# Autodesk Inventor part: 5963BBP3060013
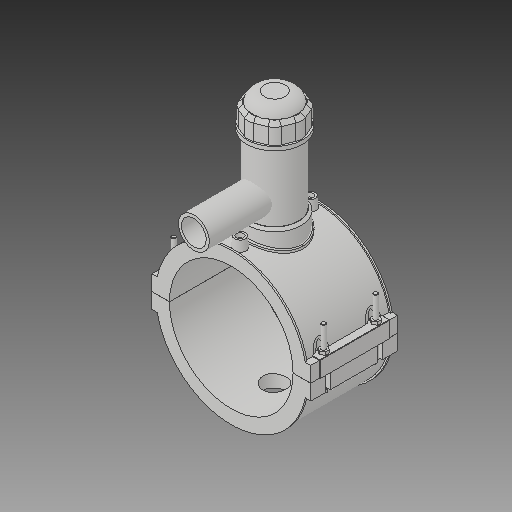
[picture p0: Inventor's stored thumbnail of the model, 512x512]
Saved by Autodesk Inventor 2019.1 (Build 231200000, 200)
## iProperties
Created: 2017-07
Part Number: 5963BBP3060013
Material: Generic
Description: PLASSON TAPPING SADDLE 6''IPS x 1 1/4''IPS
Document SubType Name: Modeling
Designer: KIM
Density: 1 g/cm^3
Appearance: Default
Author: KIM
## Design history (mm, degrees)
derived "5963BBP_5963BUP.ipt"
feature "Solid1::5963BBP_5963BUP.ipt"
feature "Solid2::5963BBP_5963BUP.ipt"
feature "Solid3::5963BBP_5963BUP.ipt"
tag "TaggingFeature1"
body "Solid1"
body "Solid2"
body "Solid3"
other parameters: "d0" = 168, "d2" = 215.9, "d3" = 42, "d4" = 118.11, "d5" = 0, "d6" = 0.1, "d8" = 0, "d19" = 6, "d20" = 6, "d21" = 70.866, "d23" = 0, "d24" = 35.433, "d26" = 0, "d27" = 3, "d28" = 3, "d29" = 3, "d30" = 56, "d31" = 6, "d32" = 0, "d33" = 0, "d34" = 0.6, "d40" = 104.832, "d41" = 75.6, "d43" = 0, "d45" = 0, "d47" = 171.666, "d70" = 15, "d72" = 0, "d73" = 6, "d75" = 5, "d76" = 0, "d77" = 8.4, "d78" = 114, "d79" = 15, "d80" = 47.244, "d82" = 5 deg, "d84" = 4, "d85" = 14, "d86" = 0, "d87" = 3, "d88" = 0, "d89" = 1, "d90" = 1, "d91" = 94.488, "d92" = 0, "d93" = 0.5, "d94" = 88.42105, "d96" = 205.632, "d97" = 2.3622, "d98" = 0, "d102" = 1.68, "d120" = 140 deg, "d121" = 24.228, "d122" = 20 deg, "d123" = 403.2, "d124" = 120.96, "d126" = 0, "d143" = 173.04, "d145" = 25.84615, "d149" = 2.52, "d150" = 28.43077, "d153" = 118.11, "d154" = 0, "d156" = 100.8, "d157" = 160 deg, "d159" = 6.72, "d161" = 2.52, "d162" = 70.866, "d163" = 0, "d164" = 84, "d167" = 16.8, "d168" = 98.34146, "d170" = 3.2805, "d172" = 0, "d173" = 1, "d175" = 84, "d176" = 20 deg, "d177" = 11.76, "d178" = 33.6, "d180" = 0, "d183" = 13.44, "d184" = 9.408, "d185" = 38.38575, "d186" = 38.38575, "d187" = 100.8, "d188" = 10.08, "d189" = 11.76, "d190" = 0, "d191" = 151.2, "d193" = 6.9984, "d194" = 4.13385, "d195" = 90 deg, "d197" = 0, "d199" = 0, "d200" = 16.8, "d202" = 0, "d203" = 177.038, "d204" = 71.82, "d205" = 52.92, "d206" = 64.26, "d207" = 132.7785, "d208" = 138.08964, "d209" = 164.64534, "d210" = 65.016, "d211" = 75.6, "d212" = 60.48, "d213" = 39.5766, "d216" = 0, "d217" = 16.8, "d218" = 16.8, "d219" = 3.36, "d222" = 168, "d224" = 0, "d225" = 65.024, "d226" = 42.1, "d227" = 33.68, "d228" = 109.982, "d230" = 5.04, "d_" = 168, "B_" = 215.9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
